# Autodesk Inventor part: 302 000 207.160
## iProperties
Created: 2008-06
Part Number: 302 000 207.160
Material: 1.0401 C15 (Einsatzst.)
Description: Ensat-S M20x1,5
Document SubType Name: Modellieren
Designer: TMT
Manufacturer: Standard
Standards Organization: Custom
Density: 1 g/cm^3
Author: TMT
Comments: Kerb Konus
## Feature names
1. Extrusion2
2. Bohrung1 [Hole]
3. Extrusion3
